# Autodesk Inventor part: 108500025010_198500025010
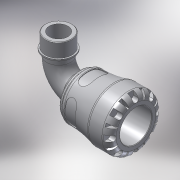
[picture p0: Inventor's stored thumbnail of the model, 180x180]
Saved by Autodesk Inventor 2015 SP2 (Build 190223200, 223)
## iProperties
Created: 2016-12
Part Number: 108500025010_198500025010
Material: PVC-Piping
Description: PLASSON 90° ELBOW WITH THREADED MALE OFFTAKE 25X1" SERIES 1
Document SubType Name: Modeling
Designer: KIM
Mass: 100.431 g
Surface Area: 250.31 cm^2
Volume: 71.7367 cm^3
Density: 1.4 g/cm^3
Appearance: Smooth - White
Author: KIM
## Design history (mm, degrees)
derived "1085.ipt"
feature "Solid1::1085.ipt"
tag "TaggingFeature1"
body "Solid1"
other parameters: "d1" = 20.16, "d2" = 25, "d3" = 31.25, "d4" = 47, "d8" = 39.95, "d13" = 6.3, "d14" = 6.3, "d15" = 0, "d17" = 360 deg, "d19" = 8 deg, "d20" = 0.5, "d21" = 0.5, "d22" = 8 deg, "d24" = 0, "d26" = 360 deg, "d33" = 4.7, "d43" = 36.66, "d51" = 0.47, "d54" = 8.75, "d55" = 5.5, "d57" = 12.348, "d58" = 0, "d74" = 0, "d78" = 48, "d82" = 0.5, "d115" = 360 deg, "d207" = 90 deg, "d228" = 7.4375, "d247" = 0.94, "d248" = 2.88, "d268" = 21.9725, "d269" = 2.88, "d270" = 74, "d276" = 33.249, "d277" = 19, "d278" = 36.5739, "d279" = 47, "d280" = 20.9, "d281" = 4.98735, "d283" = 29.9241, "d286" = 0, "d287" = 0, "d288" = 23.2743, "d290" = 3.36795, "d292" = 30 deg, "d_" = 25, "E_" = 47, "l_" = 48, "A_" = 74, "A_1" = 47, "l_2" = 19, "R_" = 33.249, "d9" = 7.875, "d11" = 47, "d12" = 31.25, "d289" = 23.2743
